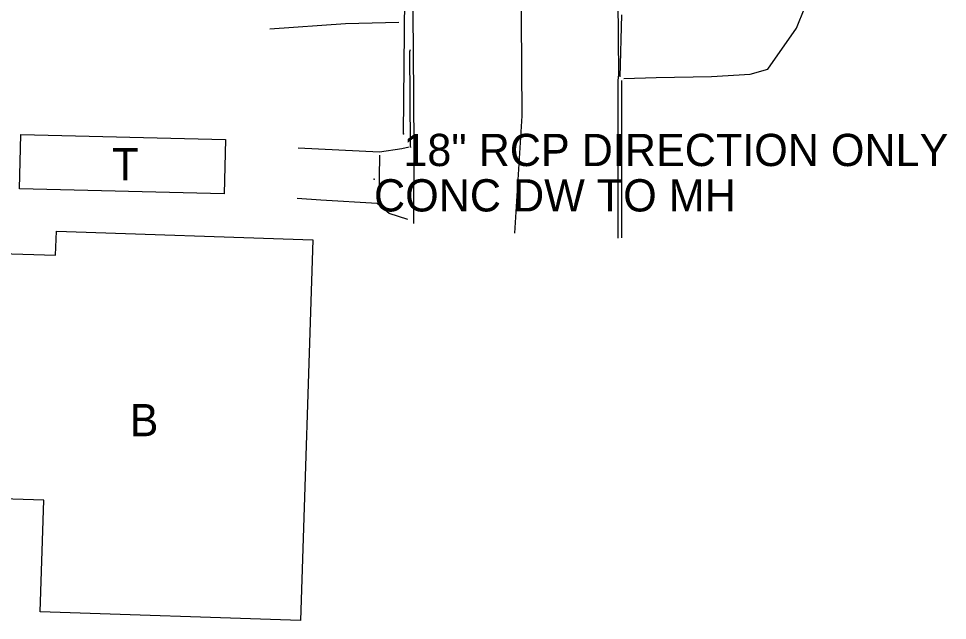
# Model space of a CAD drawing. Extents: x 1304270 to 1306561, y 1876019 to 1876752.
# Drawn here: x 1304900.2 to 1305044.2, y 1876151.4 to 1876244.8 of the extents above; entities that cross this region are included whole.
import ezdxf

# ---------------------------------------------------------------- set-up
doc = ezdxf.new("R2010")
doc.units = 0
for name, color, linetype in [('S_BUILDING', 7, 'Continuous'), ('S_BUILDING_ANNOT', 7, 'Continuous'), ('S_CURB', 7, 'Continuous'), ('S_DRIVEWAY', 7, 'Continuous'), ('S_EDGE_CONCRETE', 7, 'Continuous'), ('S_EDGE_PAVEMENT', 7, 'Continuous'), ('S_MSC_PT_SYM', 7, 'Continuous'), ('S_PAVEMENT_CROWN', 7, 'Continuous'), ('S_STORM_SEWER', 7, 'Continuous'), ('S_STORM_SEWER_ANNOT', 7, 'Continuous'), ('S_SURVEY_TEXT_ANNOT', 7, 'Continuous'), ('S_UTL_PT_SYM', 7, 'Continuous')]:
    doc.layers.add(name, color=color, linetype=linetype)

msp = doc.modelspace()

# ---------------------------------------------------------------- linework, layer by layer
at = {"layer": 'S_BUILDING'}
for points in [[(1304932.12, 1876217.58), (1304900.4, 1876218.35), (1304900.6, 1876226.77), (1304932.32, 1876226)], [(1304945.86, 1876210.45), (1304943.92, 1876151.39), (1304903.57, 1876152.71), (1304904.14, 1876170.05), (1304889.7, 1876170.52), (1304890.69, 1876200.72), (1304895.52, 1876200.56), (1304895.78, 1876208.37), (1304905.98, 1876208.03), (1304906.1, 1876211.75)]]:
    msp.add_lwpolyline(points, close=True, dxfattribs=at)
at = {"layer": 'S_CURB'}
for points in [[(1304960.95, 1876239.89), (1304960.84, 1876239.57), (1304960.94, 1876225.08), (1304960.99, 1876224.73)], [(1304993.72, 1876235.17), (1304993.68, 1876234.93), (1304993.71, 1876210.73)]]:
    msp.add_lwpolyline(points, dxfattribs=at)
at = {"layer": 'S_DRIVEWAY'}
for points in [[(1304959.17, 1876244.15), (1304950.93, 1876243.91), (1304939.19, 1876243.1)], [(1304943.58, 1876224.7), (1304956.2, 1876224.09), (1304959.63, 1876224.62), (1304960.81, 1876224.83)], [(1304960.57, 1876213.57), (1304957.69, 1876214.5), (1304955.85, 1876216.06), (1304947.1, 1876216.58), (1304943.41, 1876216.86)]]:
    msp.add_lwpolyline(points, dxfattribs=at)
at = {"layer": 'S_EDGE_CONCRETE'}
msp.add_lwpolyline([(1304956.13, 1876216.63), (1304956.23, 1876223.54)], dxfattribs=at)
at = {"layer": 'S_EDGE_PAVEMENT'}
for points in [[(1304992.58, 1876395.95), (1304992.67, 1876392.97), (1304992.89, 1876387.96), (1304993.12, 1876382.52), (1304992.95, 1876377.14), (1304992.83, 1876373.03), (1304992.83, 1876353.07), (1304992.88, 1876337.99), (1304992.93, 1876322.91), (1304993, 1876303.41), (1304993.07, 1876283.92), (1304993.07, 1876272.99), (1304992.49, 1876271.71), (1304992.46, 1876268.84), (1304992.98, 1876268.15), (1304993.15, 1876253.51), (1304993.2, 1876248.53), (1304993.13, 1876247.77), (1304993.23, 1876236.09), (1304993.14, 1876235.17), (1304993.16, 1876210.69)], [(1304961.3, 1876394.03), (1304961.33, 1876382.17), (1304961.23, 1876375.71), (1304961.22, 1876372.29), (1304960.99, 1876349.53), (1304961.06, 1876339.46), (1304960.95, 1876322), (1304961.28, 1876298.1), (1304961.25, 1876276.13), (1304961.53, 1876271.86), (1304961.62, 1876270.95), (1304961.87, 1876268.65), (1304961.43, 1876268.03), (1304961.3, 1876262.61), (1304961.21, 1876261.58), (1304961.4, 1876239.81), (1304961.49, 1876224.87), (1304961.47, 1876212.95)], [(1304994.06, 1876235.43), (1304999.1, 1876235.6), (1305007.63, 1876235.79), (1305013.63, 1876236.11), (1305016.38, 1876236.91), (1305020.82, 1876243.26), (1305022.14, 1876246.48), (1305022.34, 1876249.8), (1305021.98, 1876261.06), (1305022.37, 1876266.57), (1305022.29, 1876277.18), (1305022.28, 1876281.63), (1305022.38, 1876293.68), (1305022.35, 1876315.48), (1305022.51, 1876322.64), (1305027.56, 1876322.77)], [(1304993.51, 1876235.7), (1304993.73, 1876245.32)]]:
    msp.add_lwpolyline(points, dxfattribs=at)
at = {"layer": 'S_MSC_PT_SYM'}
msp.add_lwpolyline([(1304955.34, 1876219.83), (1304955.34, 1876219.88), (1304955.34, 1876219.83), (1304955.29, 1876219.83), (1304955.34, 1876219.83), (1304955.34, 1876219.78), (1304955.34, 1876219.83), (1304955.4, 1876219.83)], dxfattribs=at)
at = {"layer": 'S_PAVEMENT_CROWN'}
msp.add_lwpolyline([(1304978.68, 1876396.09), (1304977.75, 1876372.31), (1304977.76, 1876355.96), (1304977.78, 1876339.61), (1304977.29, 1876320.92), (1304976.79, 1876302.23), (1304977.44, 1876281.07), (1304978.08, 1876259.92), (1304978.16, 1876244.79), (1304978.24, 1876229.66), (1304977.14, 1876211.47)], dxfattribs=at)
at = {"layer": 'S_STORM_SEWER'}
msp.add_line((1304959.89, 1876226.87), (1304960.34, 1876268.78), dxfattribs=at)
at = {"layer": 'S_UTL_PT_SYM'}
msp.add_lwpolyline([(1304959.89, 1876226.87), (1304959.89, 1876226.92), (1304959.89, 1876226.87), (1304959.84, 1876226.87), (1304959.89, 1876226.87), (1304959.89, 1876226.82), (1304959.89, 1876226.87), (1304959.94, 1876226.87)], dxfattribs=at)

# ---------------------------------------------------------------- texts
at = {"layer": 'S_BUILDING_ANNOT'}
for s, p in [('T', (1304914.75, 1876219.67)), ('B', (1304917.46, 1876179.96))]:
    msp.add_text(s, height=5, dxfattribs=at).set_placement(p)
at = {"layer": 'S_STORM_SEWER_ANNOT'}
msp.add_text('18" RCP DIRECTION ONLY', height=5, dxfattribs=at).set_placement((1304959.89, 1876221.87))
at = {"layer": 'S_SURVEY_TEXT_ANNOT'}
msp.add_text('CONC DW TO MH', height=5, dxfattribs=at).set_placement((1304955.34, 1876214.83))

doc.saveas('drawing.dxf')
